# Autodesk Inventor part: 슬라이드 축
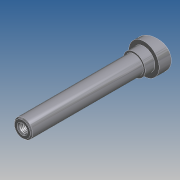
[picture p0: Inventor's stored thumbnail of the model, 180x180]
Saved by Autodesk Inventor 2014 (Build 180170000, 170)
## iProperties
Created: 2012-05
Part Number: 슬라이드 축
Document SubType Name: 모델링
Designer: SeoGD™
Mass: 169.563 g
Surface Area: 67.5859 cm^2
Volume: 21.5729 cm^3
Density: 7.86 g/cm^3
Material: 강철, 연강
Appearance: 강철
변환 표준: STEP AP214IS
파일 이름: C:\Users\SeoGD\Desktop\?쒗뿕\異?stp
전처리기: Build: 253, Release: 2010 SP1 - Date: Wed 07/29/2009
전송 단위: 밀리미터
불확실성: 0.01
Author: SeoGD™
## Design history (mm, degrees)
sketch "스케치1"
  geometry: L1 (0, 100)-(7.5, 100); L2 (7.5, 100)-(7.5, 0); L3 (7.5, 0)-(12.5, 0); L4 (12.5, 0)-(12.5, -17); L5 (12.5, -17)-(0, -17); L6 (0, -17)-(0, 100); 1 further point
  constraints: 12 end point, 2 parallel, 2 point on line, 1 perpendicular, 1 vertical
  dimensions: "d0" = 100 distance from line of L1 point (0, 0); "d1" = 15 diameter of L2 L6; "d2" = 25 diameter of L4 L6; "d3" = 17 distance of L3.end L4.end
revolve "회전1" sketch "스케치1" stored, may be unused: angle "d4" = 90 deg
sketch "스케치2"
  geometry: L1 (12.5, 0)-(12.5, -17) reference; L2 (-12.5, -17)-(12.5, -17) reference; L3 (-12.5, 0)-(-12.5, -17) reference; L4 (12.5, -5)-(-12.5, -11.699); L5 (-12.5, 0)-(12.5, 0) reference; 1 further point
  constraints: 2 end point, 2 point on line
  dimensions: "d5" = 75 deg angle of L1 L4; "d6" = 5 distance from line of L4.start L5
extrude "돌출1" cut sketch "스케치2" stored distance "d7" = 10; taper "d8" = 0 deg
chamfer "모따기1" distance "d9" = 1; stored, may be unused: second distance "d10" = 2, angle "d11" = 45 deg
fillet "모깎기1" dims "d12" = 0.5
hole "구멍1" diameter "d15" = 6.647; stored, may be unused: countersink angle "d19" = 90 deg, drill point angle "d21" = 118 deg; dims "d13" = 10, "d14" = 10, "d16" = 17, "d17" = 4, "d18" = 2, "d20" = 20
chamfer "모따기2" distance "d22" = 1; stored, may be unused: second distance "d23" = 2, angle "d24" = 45 deg
sketch "스케치3"
  geometry: C1 r 9 at (0, 0); 1 further point
  constraints: 1 centre point, 1 coincident
  dimensions: "d25" = 18 diameter of C1
extrude "돌출2" join sketch "스케치3" distance "d26" = 8; taper "d27" = 0 deg
node "솔리드1"
node "솔리드 본체"
node "곡면 본체"
node "솔리드2"
